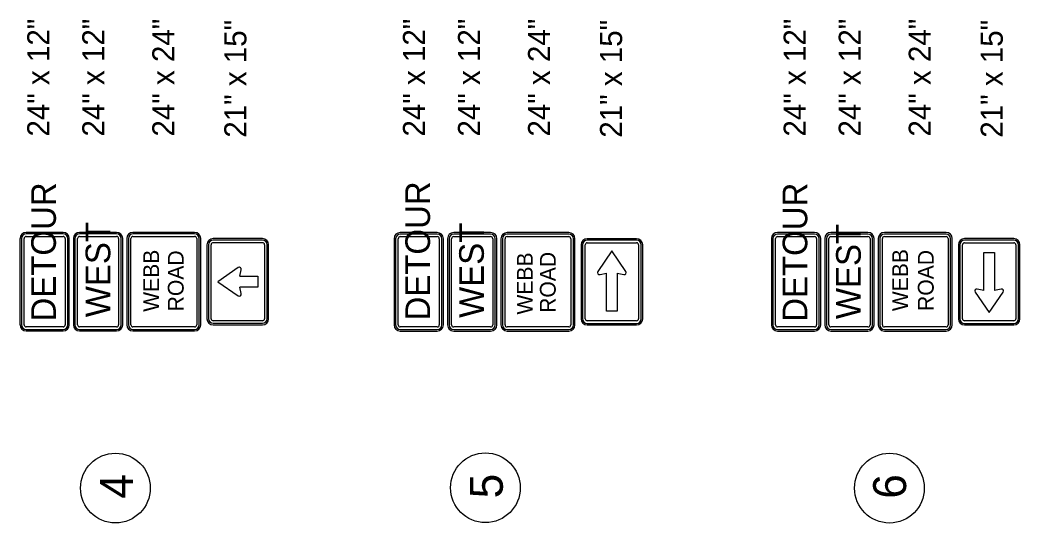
# Model space of a CAD drawing. Extents: x 1123038 to 1172987, y 554419 to 623636.
# Drawn here: x 1129352 to 1134422, y 554425 to 556976 of the extents above; entities that cross this region are included whole.
import ezdxf

# ---------------------------------------------------------------- set-up
doc = ezdxf.new("R2010")
doc.units = 0
doc.layers.add('D_Text_Standard', color=7, linetype='Continuous')
doc.layers.add('Default', color=7, linetype='Continuous')

msp = doc.modelspace()

# ---------------------------------------------------------------- linework, layer by layer
at = {"layer": 'D_Text_Standard'}
for centre in [(1129836.2, 554602), (1131711.8, 554603.7), (1133760.3, 554601.7)]:
    msp.add_circle(centre, 176.8, dxfattribs=at)
at = {"layer": 'Default'}
for p, q in [((1129352.3, 555867.4), (1129352.3, 555429.9)), ((1129360.1, 555867.4), (1129360.1, 555429.9)), ((1129373.1, 555429.9), (1129373.1, 555867.4)), ((1129571.1, 555898.6), (1129383.6, 555898.6)), ((1129571.1, 555890.8), (1129383.6, 555890.8)), ((1129383.6, 555877.8), (1129571.1, 555877.8)), ((1129581.5, 555867.4), (1129581.5, 555429.9)), ((1129594.5, 555429.9), (1129594.5, 555867.4)), ((1129602.3, 555429.9), (1129602.3, 555867.4)), ((1129623.1, 555867.4), (1129623.1, 555429.9)), ((1129631, 555867.4), (1129631, 555429.9)), ((1129644, 555429.9), (1129644, 555867.4)), ((1129841.9, 555898.6), (1129654.4, 555898.6)), ((1129841.9, 555890.8), (1129654.4, 555890.8)), ((1129654.4, 555877.8), (1129841.9, 555877.8)), ((1129852.3, 555867.4), (1129852.3, 555429.9)), ((1129865.3, 555429.9), (1129865.3, 555867.4)), ((1129873.1, 555429.9), (1129873.1, 555867.4)), ((1129894, 555867.4), (1129894, 555429.9)), ((1129901.8, 555867.4), (1129901.8, 555429.9)), ((1129914.8, 555429.9), (1129914.8, 555867.4)), ((1130237.7, 555898.6), (1129925.2, 555898.6)), ((1130237.7, 555890.8), (1129925.2, 555890.8)), ((1129925.2, 555877.8), (1130237.7, 555877.8)), ((1130248.1, 555867.4), (1130248.1, 555429.9)), ((1130261.2, 555429.9), (1130261.2, 555867.4)), ((1130269, 555429.9), (1130269, 555867.4)), ((1130581.5, 555867.4), (1130331.5, 555867.4)), ((1130581.5, 555859.6), (1130331.5, 555859.6)), ((1131248.9, 555866.8), (1131248.9, 555429.3)), ((1131256.8, 555866.8), (1131256.8, 555429.3)), ((1131269.8, 555429.3), (1131269.8, 555866.8)), ((1131467.7, 555898.1), (1131280.2, 555898.1)), ((1131467.7, 555890.2), (1131280.2, 555890.2)), ((1131280.2, 555877.2), (1131467.7, 555877.2)), ((1131478.1, 555866.8), (1131478.1, 555429.3)), ((1131491.1, 555429.3), (1131491.1, 555866.8)), ((1131498.9, 555429.3), (1131498.9, 555866.8)), ((1131519.8, 555866.8), (1131519.8, 555429.3)), ((1131527.6, 555866.8), (1131527.6, 555429.3)), ((1131540.6, 555429.3), (1131540.6, 555866.8)), ((1131738.5, 555898.1), (1131551, 555898.1)), ((1131738.5, 555890.2), (1131551, 555890.2)), ((1131551, 555877.2), (1131738.5, 555877.2)), ((1131748.9, 555866.8), (1131748.9, 555429.3)), ((1131762, 555429.3), (1131762, 555866.8)), ((1131769.8, 555429.3), (1131769.8, 555866.8)), ((1131790.6, 555866.8), (1131790.6, 555429.3)), ((1131798.4, 555866.8), (1131798.4, 555429.3)), ((1131811.4, 555429.3), (1131811.4, 555866.8)), ((1132134.4, 555898.1), (1131821.9, 555898.1)), ((1132134.4, 555890.2), (1131821.9, 555890.2)), ((1131821.9, 555877.2), (1132134.4, 555877.2)), ((1132144.8, 555866.8), (1132144.8, 555429.3)), ((1132157.8, 555429.3), (1132157.8, 555866.8)), ((1132165.6, 555429.3), (1132165.6, 555866.8)), ((1132478.1, 555866.8), (1132228.1, 555866.8)), ((1132478.1, 555859), (1132228.1, 555859)), ((1133161.7, 555866.9), (1133161.7, 555429.4)), ((1133169.5, 555866.9), (1133169.5, 555429.4)), ((1133182.6, 555429.4), (1133182.6, 555866.9)), ((1133380.5, 555898.2), (1133193, 555898.2)), ((1133380.5, 555890.3), (1133193, 555890.3)), ((1133193, 555877.3), (1133380.5, 555877.3)), ((1133390.9, 555866.9), (1133390.9, 555429.4)), ((1133403.9, 555429.4), (1133403.9, 555866.9)), ((1133411.7, 555429.4), (1133411.7, 555866.9)), ((1133432.6, 555866.9), (1133432.6, 555429.4)), ((1133440.4, 555866.9), (1133440.4, 555429.4)), ((1133453.4, 555429.4), (1133453.4, 555866.9)), ((1133651.3, 555898.2), (1133463.8, 555898.2)), ((1133651.3, 555890.3), (1133463.8, 555890.3)), ((1133463.8, 555877.3), (1133651.3, 555877.3)), ((1133661.7, 555866.9), (1133661.7, 555429.4)), ((1133674.7, 555429.4), (1133674.7, 555866.9)), ((1133682.6, 555429.4), (1133682.6, 555866.9)), ((1133703.4, 555866.9), (1133703.4, 555429.4)), ((1133711.2, 555866.9), (1133711.2, 555429.4)), ((1133724.2, 555429.4), (1133724.2, 555866.9)), ((1134047.1, 555898.2), (1133734.6, 555898.2)), ((1134047.1, 555890.3), (1133734.6, 555890.3)), ((1133734.6, 555877.3), (1134047.1, 555877.3)), ((1134057.6, 555866.9), (1134057.6, 555429.4)), ((1134070.6, 555429.4), (1134070.6, 555866.9)), ((1134078.4, 555429.4), (1134078.4, 555866.9)), ((1134390.9, 555866.9), (1134140.9, 555866.9)), ((1134390.9, 555859.1), (1134140.9, 555859.1)), ((1130300.2, 555836.1), (1130300.2, 555461.1)), ((1130308, 555836.1), (1130308, 555461.1)), ((1130321.1, 555461.1), (1130321.1, 555836.1)), ((1130331.5, 555846.6), (1130581.5, 555846.6)), ((1130591.9, 555836.1), (1130591.9, 555461.1)), ((1130604.9, 555461.1), (1130604.9, 555836.1)), ((1130612.7, 555461.1), (1130612.7, 555836.1)), ((1132196.9, 555835.6), (1132196.9, 555460.6)), ((1132204.7, 555835.6), (1132204.7, 555460.6)), ((1132217.7, 555460.6), (1132217.7, 555835.6)), ((1132228.1, 555846), (1132478.1, 555846)), ((1132488.5, 555835.6), (1132488.5, 555460.6)), ((1132501.6, 555460.6), (1132501.6, 555835.6)), ((1132509.4, 555460.6), (1132509.4, 555835.6)), ((1134109.6, 555835.7), (1134109.6, 555460.7)), ((1134117.5, 555835.7), (1134117.5, 555460.7)), ((1134130.5, 555460.7), (1134130.5, 555835.7)), ((1134140.9, 555846.1), (1134390.9, 555846.1)), ((1134401.3, 555835.7), (1134401.3, 555460.7)), ((1134414.3, 555460.7), (1134414.3, 555835.7)), ((1134422.1, 555460.7), (1134422.1, 555835.7)), ((1132353.1, 555804.3), (1132281.8, 555700.5)), ((1132424.4, 555700.5), (1132353.1, 555804.3)), ((1134238.5, 555796.6), (1134293.2, 555796.6)), ((1134238.5, 555603.9), (1134238.5, 555796.6)), ((1134293.2, 555796.6), (1134293.2, 555603.9)), ((1130458.7, 555719.9), (1130354.9, 555648.6)), ((1130466.9, 555676), (1130474.4, 555708.8)), ((1130466.9, 555676), (1130558, 555676)), ((1130558, 555676), (1130558, 555621.3)), ((1132292.9, 555684.8), (1132325.8, 555692.3)), ((1132325.8, 555499.6), (1132325.8, 555692.3)), ((1132380.5, 555692.3), (1132413.3, 555684.8)), ((1132380.5, 555692.3), (1132380.5, 555499.6)), ((1130354.9, 555648.6), (1130458.7, 555577.3)), ((1130474.4, 555588.5), (1130466.9, 555621.3)), ((1130558, 555621.3), (1130466.9, 555621.3)), ((1134238.5, 555603.9), (1134205.7, 555611.4)), ((1134326.1, 555611.4), (1134293.2, 555603.9)), ((1134194.6, 555595.7), (1134265.9, 555491.9)), ((1134265.9, 555491.9), (1134337.2, 555595.7)), ((1130581.5, 555450.7), (1130331.5, 555450.7)), ((1132478.1, 555450.1), (1132228.1, 555450.1)), ((1132380.5, 555499.6), (1132325.8, 555499.6)), ((1134390.9, 555450.2), (1134140.9, 555450.2)), ((1129571.1, 555419.5), (1129383.6, 555419.5)), ((1129383.6, 555406.5), (1129571.1, 555406.5)), ((1129841.9, 555419.5), (1129654.4, 555419.5)), ((1129654.4, 555406.5), (1129841.9, 555406.5)), ((1130237.7, 555419.5), (1129925.2, 555419.5)), ((1129925.2, 555406.5), (1130237.7, 555406.5)), ((1130331.5, 555437.7), (1130581.5, 555437.7)), ((1130331.5, 555429.9), (1130581.5, 555429.9)), ((1131467.7, 555418.9), (1131280.2, 555418.9)), ((1131280.2, 555405.9), (1131467.7, 555405.9)), ((1131738.5, 555418.9), (1131551, 555418.9)), ((1131551, 555405.9), (1131738.5, 555405.9)), ((1132134.4, 555418.9), (1131821.9, 555418.9)), ((1131821.9, 555405.9), (1132134.4, 555405.9)), ((1132228.1, 555437.1), (1132478.1, 555437.1)), ((1132228.1, 555429.3), (1132478.1, 555429.3)), ((1133380.5, 555419), (1133193, 555419)), ((1133193, 555406), (1133380.5, 555406)), ((1133651.3, 555419), (1133463.8, 555419)), ((1133463.8, 555406), (1133651.3, 555406)), ((1134047.1, 555419), (1133734.6, 555419)), ((1133734.6, 555406), (1134047.1, 555406)), ((1134140.9, 555437.2), (1134390.9, 555437.2)), ((1134140.9, 555429.4), (1134390.9, 555429.4)), ((1129383.6, 555398.6), (1129571.1, 555398.6)), ((1129654.4, 555398.6), (1129841.9, 555398.6)), ((1129925.2, 555398.6), (1130237.7, 555398.6)), ((1131280.2, 555398.1), (1131467.7, 555398.1)), ((1131551, 555398.1), (1131738.5, 555398.1)), ((1131821.9, 555398.1), (1132134.4, 555398.1)), ((1133193, 555398.2), (1133380.5, 555398.2)), ((1133463.8, 555398.2), (1133651.3, 555398.2)), ((1133734.6, 555398.2), (1134047.1, 555398.2))]:
    msp.add_line(p, q, dxfattribs=at)
for centre, radius, start, end in [((1129383.6, 555867.4), 31.2, 90, 180), ((1129383.6, 555867.4), 23.4, 90, 180), ((1129383.6, 555867.4), 10.4, 90, 180), ((1129571.1, 555867.4), 31.2, 0, 90), ((1129571.1, 555867.4), 23.4, 0, 90), ((1129571.1, 555867.4), 10.4, 0, 90), ((1129654.4, 555867.4), 31.2, 90, 180), ((1129654.4, 555867.4), 23.4, 90, 180), ((1129654.4, 555867.4), 10.4, 90, 180), ((1129841.9, 555867.4), 31.2, 0, 90), ((1129841.9, 555867.4), 23.4, 0, 90), ((1129841.9, 555867.4), 10.4, 0, 90), ((1129925.2, 555867.4), 31.2, 90, 180), ((1129925.2, 555867.4), 23.4, 90, 180), ((1129925.2, 555867.4), 10.4, 90, 180), ((1130237.7, 555867.4), 31.2, 0, 90), ((1130237.7, 555867.4), 23.4, 0, 90), ((1130237.7, 555867.4), 10.4, 0, 90), ((1130331.5, 555836.1), 31.2, 90, 180), ((1130331.5, 555836.1), 23.4, 90, 180), ((1130581.5, 555836.1), 31.2, 0, 90), ((1130581.5, 555836.1), 23.4, 0, 90), ((1131280.2, 555866.8), 31.2, 90, 180), ((1131280.2, 555866.8), 23.4, 90, 180), ((1131280.2, 555866.8), 10.4, 90, 180), ((1131467.7, 555866.8), 31.2, 0, 90), ((1131467.7, 555866.8), 23.4, 0, 90), ((1131467.7, 555866.8), 10.4, 0, 90), ((1131551, 555866.8), 31.2, 90, 180), ((1131551, 555866.8), 23.4, 90, 180), ((1131551, 555866.8), 10.4, 90, 180), ((1131738.5, 555866.8), 31.2, 0, 90), ((1131738.5, 555866.8), 23.4, 0, 90), ((1131738.5, 555866.8), 10.4, 0, 90), ((1131821.9, 555866.8), 31.2, 90, 180), ((1131821.9, 555866.8), 23.4, 90, 180), ((1131821.9, 555866.8), 10.4, 90, 180), ((1132134.4, 555866.8), 31.2, 0, 90), ((1132134.4, 555866.8), 23.4, 0, 90), ((1132134.4, 555866.8), 10.4, 0, 90), ((1132228.1, 555835.6), 31.2, 90, 180), ((1132228.1, 555835.6), 23.4, 90, 180), ((1132478.1, 555835.6), 31.2, 0, 90), ((1132478.1, 555835.6), 23.4, 0, 90), ((1133193, 555866.9), 31.2, 90, 180), ((1133193, 555866.9), 23.4, 90, 180), ((1133193, 555866.9), 10.4, 90, 180), ((1133380.5, 555866.9), 31.2, 0, 90), ((1133380.5, 555866.9), 23.4, 0, 90), ((1133380.5, 555866.9), 10.4, 0, 90), ((1133463.8, 555866.9), 31.2, 90, 180), ((1133463.8, 555866.9), 23.4, 90, 180), ((1133463.8, 555866.9), 10.4, 90, 180), ((1133651.3, 555866.9), 31.2, 0, 90), ((1133651.3, 555866.9), 23.4, 0, 90), ((1133651.3, 555866.9), 10.4, 0, 90), ((1133734.6, 555866.9), 31.2, 90, 180), ((1133734.6, 555866.9), 23.4, 90, 180), ((1133734.6, 555866.9), 10.4, 90, 180), ((1134047.1, 555866.9), 31.2, 0, 90), ((1134047.1, 555866.9), 23.4, 0, 90), ((1134047.1, 555866.9), 10.4, 0, 90), ((1134140.9, 555835.7), 31.2, 90, 180), ((1134140.9, 555835.7), 23.4, 90, 180), ((1134390.9, 555835.7), 31.2, 0, 90), ((1134390.9, 555835.7), 23.4, 0, 90), ((1130331.5, 555836.1), 10.4, 90, 180), ((1130581.5, 555836.1), 10.4, 0, 90), ((1132228.1, 555835.6), 10.4, 90, 180), ((1132478.1, 555835.6), 10.4, 0, 90), ((1134140.9, 555835.7), 10.4, 90, 180), ((1134390.9, 555835.7), 10.4, 0, 90), ((1130464.3, 555711.1), 10.4, 347.0497, 122.2757), ((1132290.6, 555694.9), 10.4, 147.7244, 282.9503), ((1132415.6, 555694.9), 10.4, 257.0497, 32.2757), ((1134203.4, 555601.3), 10.4, 77.0497, 212.2757), ((1134328.4, 555601.3), 10.4, 327.7244, 102.9504), ((1130464.3, 555586.1), 10.4, 237.7244, 12.9504), ((1130331.5, 555461.1), 31.2, 180, 270), ((1130331.5, 555461.1), 23.4, 180, 270), ((1130331.5, 555461.1), 10.4, 180, 270), ((1130581.5, 555461.1), 31.2, 270, 0), ((1130581.5, 555461.1), 23.4, 270, 0), ((1130581.5, 555461.1), 10.4, 270, 0), ((1132228.1, 555460.6), 31.2, 180, 270), ((1132228.1, 555460.6), 23.4, 180, 270), ((1132228.1, 555460.6), 10.4, 180, 270), ((1132478.1, 555460.6), 31.2, 270, 0), ((1132478.1, 555460.6), 23.4, 270, 0), ((1132478.1, 555460.6), 10.4, 270, 0), ((1134140.9, 555460.7), 31.2, 180, 270), ((1134140.9, 555460.7), 23.4, 180, 270), ((1134140.9, 555460.7), 10.4, 180, 270), ((1134390.9, 555460.7), 31.2, 270, 0), ((1134390.9, 555460.7), 23.4, 270, 0), ((1134390.9, 555460.7), 10.4, 270, 0), ((1129383.6, 555429.9), 31.2, 180, 270), ((1129383.6, 555429.9), 23.4, 180, 270), ((1129383.6, 555429.9), 10.4, 180, 270), ((1129571.1, 555429.9), 31.2, 270, 0), ((1129571.1, 555429.9), 23.4, 270, 0), ((1129571.1, 555429.9), 10.4, 270, 0), ((1129654.4, 555429.9), 31.2, 180, 270), ((1129654.4, 555429.9), 23.4, 180, 270), ((1129654.4, 555429.9), 10.4, 180, 270), ((1129841.9, 555429.9), 31.2, 270, 0), ((1129841.9, 555429.9), 23.4, 270, 0), ((1129841.9, 555429.9), 10.4, 270, 0), ((1129925.2, 555429.9), 31.2, 180, 270), ((1129925.2, 555429.9), 23.4, 180, 270), ((1129925.2, 555429.9), 10.4, 180, 270), ((1130237.7, 555429.9), 31.2, 270, 0), ((1130237.7, 555429.9), 23.4, 270, 0), ((1130237.7, 555429.9), 10.4, 270, 0), ((1131280.2, 555429.3), 31.2, 180, 270), ((1131280.2, 555429.3), 23.4, 180, 270), ((1131280.2, 555429.3), 10.4, 180, 270), ((1131467.7, 555429.3), 31.2, 270, 0), ((1131467.7, 555429.3), 23.4, 270, 0), ((1131467.7, 555429.3), 10.4, 270, 0), ((1131551, 555429.3), 31.2, 180, 270), ((1131551, 555429.3), 23.4, 180, 270), ((1131551, 555429.3), 10.4, 180, 270), ((1131738.5, 555429.3), 31.2, 270, 0), ((1131738.5, 555429.3), 23.4, 270, 0), ((1131738.5, 555429.3), 10.4, 270, 0), ((1131821.9, 555429.3), 31.2, 180, 270), ((1131821.9, 555429.3), 23.4, 180, 270), ((1131821.9, 555429.3), 10.4, 180, 270), ((1132134.4, 555429.3), 31.2, 270, 0), ((1132134.4, 555429.3), 23.4, 270, 0), ((1132134.4, 555429.3), 10.4, 270, 0), ((1133193, 555429.4), 31.2, 180, 270), ((1133193, 555429.4), 23.4, 180, 270), ((1133193, 555429.4), 10.4, 180, 270), ((1133380.5, 555429.4), 31.2, 270, 0), ((1133380.5, 555429.4), 23.4, 270, 0), ((1133380.5, 555429.4), 10.4, 270, 0), ((1133463.8, 555429.4), 31.2, 180, 270), ((1133463.8, 555429.4), 23.4, 180, 270), ((1133463.8, 555429.4), 10.4, 180, 270), ((1133651.3, 555429.4), 31.2, 270, 0), ((1133651.3, 555429.4), 23.4, 270, 0), ((1133651.3, 555429.4), 10.4, 270, 0), ((1133734.6, 555429.4), 31.2, 180, 270), ((1133734.6, 555429.4), 23.4, 180, 270), ((1133734.6, 555429.4), 10.4, 180, 270), ((1134047.1, 555429.4), 31.2, 270, 0), ((1134047.1, 555429.4), 23.4, 270, 0), ((1134047.1, 555429.4), 10.4, 270, 0)]:
    msp.add_arc(centre, radius, start, end, dxfattribs=at)

# ---------------------------------------------------------------- texts
at = {"layer": 'D_Text_Standard'}
for s, height, p in [('24" x 12"', 111.99, (1129501, 556384.6)), ('24" x 12"', 111.99, (1129780.1, 556384.6)), ('24" x 24"', 111.99, (1130135.1, 556384.6)), ('24" x 12"', 111.99, (1131405.8, 556384.6)), ('24" x 12"', 111.99, (1131684.9, 556384.6)), ('24" x 24"', 111.99, (1132039.9, 556384.6)), ('24" x 12"', 111.99, (1133335.9, 556384.6)), ('24" x 12"', 111.99, (1133615, 556384.6)), ('24" x 24"', 111.99, (1133970, 556384.6)), ('21" x 15"', 111.99, (1130500.1, 556378.8)), ('21" x 15"', 111.99, (1132404.9, 556378.8)), ('21" x 15"', 111.99, (1134335, 556378.8)), ('4', 167.1, (1129924.6, 554548.4)), ('5', 167.1, (1131800, 554550.1)), ('6', 167.1, (1133844.8, 554548.1))]:
    msp.add_text(s, height=height, rotation=90, dxfattribs=at).set_placement(p)
at = {"layer": 'Default'}
for s, height, p in [('DETOUR', 125, (1129534.3, 555446.6)), ('DETOUR', 125, (1131431, 555451.8)), ('DETOUR', 125, (1133343.8, 555445.1)), ('WEST', 125, (1129810, 555468.4)), ('WEST', 125, (1131703.9, 555465.1)), ('WEST', 125, (1133614.8, 555459)), ('WEBB', 80, (1130057.2, 555495.9)), ('WEBB', 80, (1133854.1, 555499.1)), ('ROAD', 80, (1130182, 555498.3)), ('WEBB', 80, (1131951.8, 555481.9)), ('ROAD', 80, (1132068.2, 555490.6)), ('ROAD', 80, (1133984.5, 555500.3))]:
    msp.add_text(s, height=height, rotation=90, dxfattribs=at).set_placement(p)

doc.saveas('drawing.dxf')
